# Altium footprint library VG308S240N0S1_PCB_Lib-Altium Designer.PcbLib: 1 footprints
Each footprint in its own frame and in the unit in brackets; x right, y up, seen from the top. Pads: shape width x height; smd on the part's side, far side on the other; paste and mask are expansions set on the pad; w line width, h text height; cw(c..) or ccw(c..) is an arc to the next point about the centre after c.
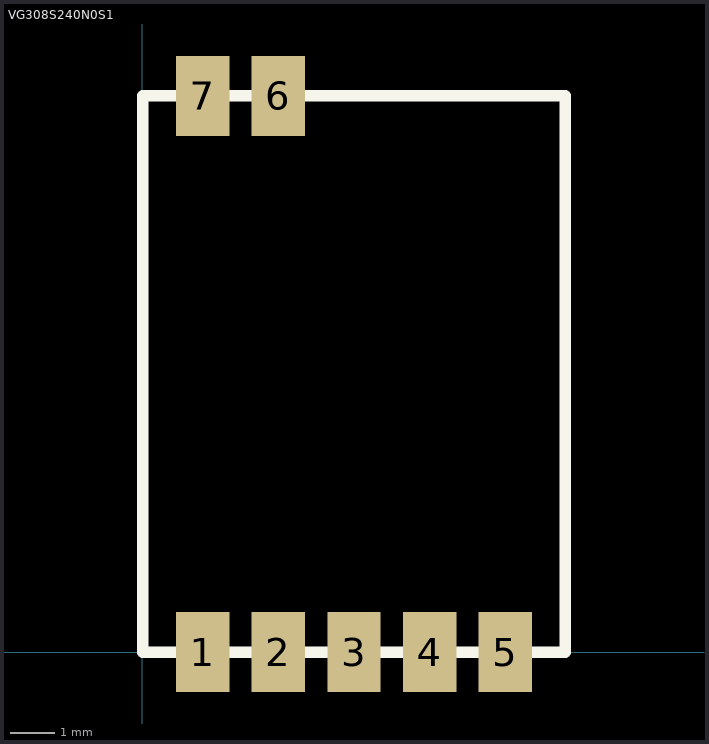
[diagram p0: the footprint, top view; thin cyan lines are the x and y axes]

## VG308S240N0S1 [mm]
pads (7):
  rect 1.2x1.8 smd: 1(1.363,0) 2(3.063,0) 3(4.763,0) 4(6.462,0) 5(8.162,0) 6(3.063,12.5) 7(1.363,12.5)
Top Overlay:
  lines w0.254: 0.012,0 9.512,0 9.512,12.5 0.012,12.5 0.012,0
